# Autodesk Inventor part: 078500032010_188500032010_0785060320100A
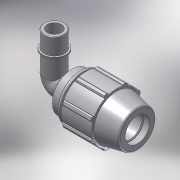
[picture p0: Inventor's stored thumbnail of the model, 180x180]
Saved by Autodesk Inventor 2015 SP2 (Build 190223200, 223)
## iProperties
Created: 2017-02
Part Number: 078500032010_188500032010_0785060320100A
Material: PVC-Piping
Description: PLASSON 90° ELBOW MALE ADAPTOR 32-1"
Document SubType Name: Modeling
Designer: KIM
Mass: 92.6774 g
Surface Area: 199.44 cm^2
Volume: 66.1981 cm^3
Density: 1.4 g/cm^3
Appearance: Smooth - White
Author: KIM
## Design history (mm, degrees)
derived "07850.ipt"
feature "Solid1::07850.ipt"
tag "TaggingFeature1"
body "Solid1"
other parameters: "d2" = 32, "d4" = 8.66667, "d5" = 26, "d7" = 64, "d9" = 14.85714, "d11" = 3.46667, "d13" = 120 deg, "d14" = 44.8, "d15" = 12 deg, "d16" = 55.68, "d18" = 1.6, "d19" = 35 deg, "d20" = 17.5 deg, "d21" = 59.52, "d23" = 0, "d25" = 360 deg, "d27" = 1.28, "d33" = 0.64, "d42" = 38.48, "d43" = 1.92, "d46" = 0.96, "d51" = 104, "d68" = 3.46667, "d72" = 55, "d73" = 33.249, "d75" = 38.23635, "d76" = 23.2743, "d77" = 22, "d79" = 13.2996, "d80" = 0.99747, "d83" = 0, "d84" = 0, "d91" = 48, "d93" = 67, "d94" = 33.249, "d95" = 23.2743, "d96" = 10.4, "d97" = 50 deg, "d_" = 32, "E_" = 64, "A_" = 104, "l_" = 67, "A_1" = 55, "R_" = 33.249
